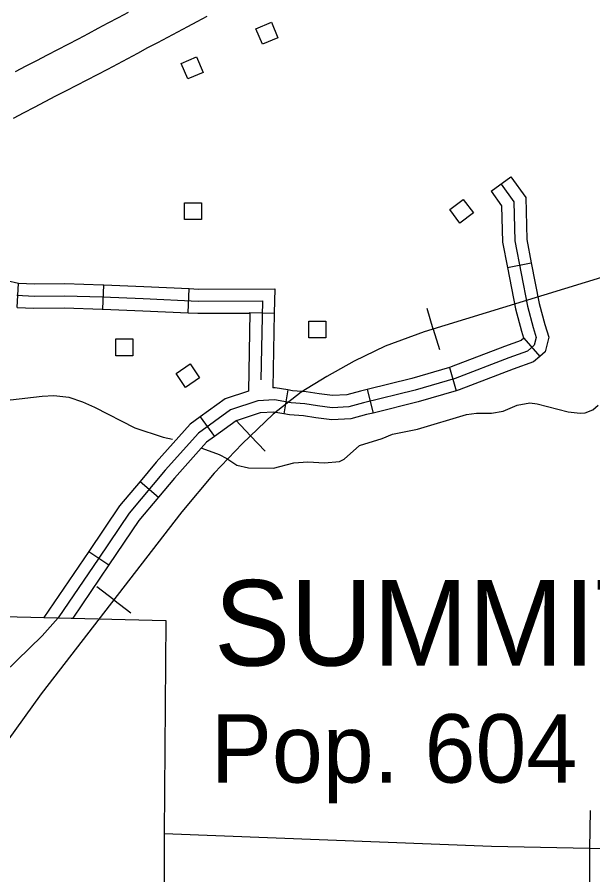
# Model space of a CAD drawing. Extents: x 1370130 to 1380143, y 377636 to 380256.
# Drawn here: x 1378630.1 to 1378779.4, y 378462.7 to 378685.1 of the extents above; entities that cross this region are included whole.
import ezdxf

# ---------------------------------------------------------------- set-up
doc = ezdxf.new("R2010")
doc.units = 0
for name, color, linetype in [('Level 10', 7, 'Continuous'), ('Level 32', 7, 'Continuous'), ('Level 34', 7, 'Continuous'), ('Level 35', 7, 'Continuous'), ('Level 40', 7, 'Continuous'), ('Level 5', 7, 'Continuous'), ('Level 56', 7, 'Continuous'), ('Level 6', 7, 'Continuous')]:
    doc.layers.add(name, color=color, linetype=linetype)

msp = doc.modelspace()

# ---------------------------------------------------------------- linework, layer by layer
at = {"layer": 'Level 10'}
for p, q in [((1378656.35, 378684.95), (1378658.96, 378686.34)), ((1378653.74, 378683.57), (1378656.35, 378684.95)), ((1378679.24, 378685.21), (1378676.72, 378683.89)), ((1378648.56, 378680.81), (1378651.14, 378682.18)), ((1378651.14, 378682.18), (1378653.74, 378683.57)), ((1378674.23, 378682.56), (1378671.69, 378681.2)), ((1378676.72, 378683.89), (1378674.23, 378682.56)), ((1378645.99, 378679.45), (1378648.56, 378680.81)), ((1378669.1, 378679.83), (1378666.49, 378678.45)), ((1378671.69, 378681.2), (1378669.1, 378679.83)), ((1378640.68, 378676.69), (1378643.36, 378678.08)), ((1378643.36, 378678.08), (1378645.99, 378679.45)), ((1378666.49, 378678.45), (1378663.89, 378677.07)), ((1378635.21, 378673.87), (1378637.97, 378675.29)), ((1378637.97, 378675.29), (1378640.68, 378676.69)), ((1378661.27, 378675.68), (1378658.67, 378674.3)), ((1378663.89, 378677.07), (1378661.27, 378675.68)), ((1378632.43, 378672.43), (1378635.21, 378673.87)), ((1378656.09, 378672.92), (1378653.49, 378671.53)), ((1378658.67, 378674.3), (1378656.09, 378672.92)), ((1378629.67, 378670.99), (1378632.43, 378672.43)), ((1378653.49, 378671.53), (1378650.86, 378670.14)), ((1378648.2, 378668.77), (1378645.52, 378667.37)), ((1378650.86, 378670.14), (1378648.2, 378668.77)), ((1378645.52, 378667.37), (1378642.78, 378665.95)), ((1378640.02, 378664.54), (1378637.28, 378663.12)), ((1378642.78, 378665.95), (1378640.02, 378664.54)), ((1378634.54, 378661.68), (1378631.81, 378660.25)), ((1378637.28, 378663.12), (1378634.54, 378661.68)), ((1378631.81, 378660.25), (1378629.07, 378658.82))]:
    msp.add_line(p, q, dxfattribs=at)
at = {"layer": 'Level 32'}
for p, q in [((1378752.99, 378639.94), (1378758.1, 378643.63)), ((1378757.22, 378620.19), (1378763.4, 378621.39)), ((1378630.1, 378609.83), (1378630.42, 378616.12)), ((1378652.29, 378609.39), (1378652.56, 378615.68)), ((1378674.43, 378608.4), (1378674.73, 378614.7)), ((1378690.46, 378608.48), (1378696.76, 378608.37)), ((1378761.48, 378601.87), (1378765.58, 378597.09)), ((1378742.16, 378594.24), (1378743.93, 378588.2)), ((1378700.29, 378588.42), (1378699.2, 378582.21)), ((1378720.87, 378588.56), (1378722.38, 378582.44)), ((1378677.56, 378581.45), (1378681.26, 378576.35)), ((1378661.96, 378564.72), (1378666.78, 378560.66)), ((1378648.68, 378546.57), (1378653.91, 378543.06))]:
    msp.add_line(p, q, dxfattribs=at)
for points in [[(1378755.55, 378641.79), (1378758.84, 378637.23), (1378759.09, 378627.1), (1378762.38, 378610.14), (1378763.9, 378604.57), (1378764.66, 378602.03), (1378764.15, 378600.01), (1378762.38, 378598.49), (1378757.57, 378596.72), (1378743.65, 378591.4), (1378733.28, 378588.36), (1378719.87, 378585.07), (1378716.07, 378584.06), (1378711.77, 378583.8), (1378707.97, 378584.31), (1378704.68, 378584.82), (1378701.14, 378585.07), (1378696.84, 378585.83), (1378692.54, 378585.58), (1378685.45, 378583.3), (1378677.1, 378577.22), (1378668.5, 378567.6), (1378659.13, 378556.46), (1378651.29, 378544.81), (1378640.77, 378529.36)], [(1378758.1, 378643.63), (1378761.96, 378638.28), (1378762.23, 378627.44), (1378763.4, 378621.39)], [(1378752.99, 378639.94), (1378755.71, 378636.18), (1378755.95, 378626.76), (1378757.22, 378620.19)], [(1378608.42, 378617.41), (1378609.35, 378619.85), (1378610.88, 378621.69), (1378612.97, 378622.64), (1378615.22, 378622.64), (1378616.61, 378622.09), (1378618.14, 378621.37), (1378621.24, 378619.38), (1378623.98, 378618.1), (1378627.42, 378616.76), (1378630.46, 378616.12), (1378630.42, 378616.12)], [(1378757.22, 378620.19), (1378759.31, 378609.42), (1378760.87, 378603.7), (1378761.39, 378601.96), (1378761.34, 378601.75), (1378761.48, 378601.87)], [(1378763.4, 378621.39), (1378765.45, 378610.85), (1378766.93, 378605.43), (1378767.92, 378602.11), (1378766.96, 378598.27), (1378765.58, 378597.09)], [(1378630.42, 378616.12), (1378634.56, 378615.92), (1378642.43, 378615.99), (1378652.34, 378615.69), (1378652.56, 378615.68)], [(1378652.56, 378615.68), (1378662.93, 378615.25), (1378674.73, 378614.7)], [(1378630.06, 378612.99), (1378634.49, 378612.77), (1378642.4, 378612.84), (1378652.22, 378612.54), (1378662.79, 378612.1), (1378677.05, 378611.44), (1378693.67, 378611.51), (1378693.3, 378591.03)], [(1378674.73, 378614.7), (1378677.11, 378614.59), (1378696.88, 378614.67), (1378696.76, 378608.37)], [(1378630.1, 378609.83), (1378634.43, 378609.62), (1378642.36, 378609.69), (1378652.11, 378609.4), (1378652.29, 378609.39)], [(1378652.29, 378609.39), (1378662.65, 378608.95), (1378674.43, 378608.4)], [(1378674.43, 378608.4), (1378676.98, 378608.29), (1378690.46, 378608.35), (1378690.46, 378608.48)], [(1378690.46, 378608.48), (1378690.1, 378588.1)], [(1378696.76, 378608.37), (1378696.41, 378588.96)], [(1378761.48, 378601.87), (1378760.76, 378601.25), (1378756.46, 378599.67), (1378742.65, 378594.39), (1378742.16, 378594.24)], [(1378765.58, 378597.09), (1378764, 378595.73), (1378758.68, 378593.77), (1378744.66, 378588.41), (1378743.93, 378588.2)], [(1378742.16, 378594.24), (1378732.46, 378591.4), (1378720.87, 378588.56)], [(1378700.29, 378588.42), (1378697.02, 378589), (1378696.41, 378588.96)], [(1378720.87, 378588.56), (1378719.09, 378588.12), (1378715.57, 378587.18), (1378711.89, 378586.97), (1378708.42, 378587.43), (1378705.04, 378587.95), (1378701.53, 378588.2), (1378700.29, 378588.42)], [(1378690.1, 378588.1), (1378684.01, 378586.14), (1378677.56, 378581.45)], [(1378743.93, 378588.2), (1378734.1, 378585.32), (1378722.38, 378582.44)], [(1378699.2, 378582.21), (1378696.66, 378582.66), (1378693.12, 378582.45), (1378686.9, 378580.45), (1378681.26, 378576.35)], [(1378722.38, 378582.44), (1378720.65, 378582.02), (1378716.57, 378580.93), (1378711.65, 378580.64), (1378707.53, 378581.19), (1378704.33, 378581.68), (1378700.75, 378581.94), (1378699.2, 378582.21)], [(1378677.56, 378581.45), (1378674.98, 378579.57), (1378666.12, 378569.66), (1378661.96, 378564.72)], [(1378681.26, 378576.35), (1378679.23, 378574.87), (1378670.88, 378565.54), (1378666.78, 378560.66)], [(1378661.96, 378564.72), (1378656.62, 378558.36), (1378648.68, 378546.57)], [(1378666.78, 378560.66), (1378661.65, 378554.56), (1378653.91, 378543.06)], [(1378648.68, 378546.57), (1378637.02, 378529.45), (1378644.52, 378529.27)], [(1378653.91, 378543.06), (1378653.9, 378543.05), (1378644.52, 378529.27)]]:
    msp.add_lwpolyline(points, dxfattribs=at)
at = {"layer": 'Level 34'}
msp.add_lwpolyline([(1378640.77, 378529.36), (1378636.57, 378524.7), (1378626.74, 378515.08)], dxfattribs=at)
at = {"layer": 'Level 35'}
for points in [[(1378620.81, 378587.18), (1378623.05, 378586.51), (1378628.36, 378585.86), (1378636.59, 378586.82), (1378639.6, 378586.97), (1378643.47, 378586.52), (1378647.04, 378585.35), (1378650.15, 378583.99), (1378660.61, 378578.56), (1378667.95, 378576.22), (1378670.39, 378575.64)], [(1378724.73, 378575.87), (1378727.39, 378576.95), (1378733.93, 378578.29), (1378746.63, 378582.03), (1378749.23, 378582.4), (1378753.1, 378582.39), (1378756.12, 378582.96), (1378759.74, 378584.49), (1378763.05, 378585.1), (1378764.96, 378584.8), (1378772.96, 378582.75), (1378776.03, 378582.41)], [(1378776.03, 378582.41), (1378777.34, 378582.46), (1378779.32, 378583.28), (1378780.75, 378584.47)], [(1378690.08, 378568.23), (1378696.59, 378568.16), (1378701.83, 378569.57), (1378705.43, 378569.8), (1378709.77, 378569.57), (1378713.68, 378569.91), (1378714.92, 378570.48), (1378718.88, 378574.04), (1378724.73, 378575.87)], [(1378677.99, 378573.34), (1378682.45, 378571.69), (1378684.5, 378570.67), (1378687.04, 378568.91), (1378690.08, 378568.23)]]:
    msp.add_lwpolyline(points, dxfattribs=at)
at = {"layer": 'Level 40'}
for p, q in [((1378737.99, 378604.22), (1378736.37, 378609.52)), ((1378737.99, 378604.22), (1378739.61, 378598.92)), ((1378690.6, 378576.55), (1378686.78, 378580.56)), ((1378690.6, 378576.55), (1378694.43, 378572.54)), ((1378655.15, 378534), (1378650.77, 378537.39)), ((1378655.15, 378534), (1378659.54, 378530.61))]:
    msp.add_line(p, q, dxfattribs=at)
msp.add_lwpolyline([(1379037.67, 378728.08), (1379011.37, 378711.43), (1378979.03, 378691.2), (1378955.14, 378676.03), (1378944.66, 378670.61), (1378929.78, 378663.71), (1378913.88, 378657.74), (1378900.65, 378653.42), (1378885.95, 378648.73), (1378808.4, 378625.74), (1378735.63, 378603.5), (1378725.52, 378599.73), (1378717.44, 378595.87), (1378710.36, 378591.91), (1378703.75, 378587.87), (1378696.49, 378582.17), (1378688.4, 378574.44), (1378681.14, 378566.81), (1378672.78, 378556.79), (1378636.31, 378509.63), (1378616.64, 378482.33), (1378598.45, 378460.26)], dxfattribs=at)
msp.add_lwpolyline([(1379037.67, 378728.08), (1379011.37, 378711.43), (1378979.03, 378691.2), (1378955.14, 378676.03), (1378944.66, 378670.61), (1378929.78, 378663.71), (1378913.88, 378657.74), (1378900.65, 378653.42), (1378885.95, 378648.73), (1378808.4, 378625.74), (1378735.63, 378603.5), (1378725.52, 378599.73), (1378717.44, 378595.87), (1378710.36, 378591.91), (1378703.75, 378587.87), (1378696.49, 378582.17), (1378688.4, 378574.44), (1378681.14, 378566.81), (1378672.78, 378556.79), (1378636.31, 378509.63), (1378616.64, 378482.33), (1378598.45, 378460.26)], dxfattribs=at)
at = {"layer": 'Level 5'}
for points in [[(1378778.64, 378479.41), (1378778.51, 378469.55)], [(1378778.51, 378469.55), (1378753.11, 378470.11), (1378668.24, 378473.37)], [(1378778.51, 378469.55), (1378778.23, 378387.25)], [(1378891.42, 378467.73), (1378834.76, 378468.48), (1378778.51, 378469.55)]]:
    msp.add_lwpolyline(points, dxfattribs=at)
at = {"layer": 'Level 56'}
for points in [[(1378693.67, 378678.03), (1378691.98, 378682.06), (1378696.03, 378683.75), (1378697.72, 378679.72)], [(1378672.6, 378673.09), (1378676.62, 378674.79), (1378678.34, 378670.76), (1378674.31, 378669.05)], [(1378745.75, 378637.83), (1378748.37, 378634.33), (1378744.86, 378631.7), (1378742.24, 378635.2)], [(1378673.47, 378632.57), (1378673.47, 378636.94), (1378677.86, 378636.94), (1378677.86, 378632.57)], [(1378705.72, 378601.89), (1378705.72, 378606.26), (1378710.1, 378606.26), (1378710.1, 378601.89)], [(1378655.68, 378597.3), (1378655.68, 378601.67), (1378660.07, 378601.67), (1378660.07, 378597.3)], [(1378674.95, 378595.15), (1378677.41, 378591.54), (1378673.78, 378589.07), (1378671.32, 378592.69)]]:
    msp.add_lwpolyline(points, close=True, dxfattribs=at)
at = {"layer": 'Level 6'}
msp.add_lwpolyline([(1378577.46, 378530.92), (1378668.67, 378528.67), (1378668.24, 378473.37), (1378668.14, 378390.77), (1378778.23, 378387.25), (1378778.14, 378362.19)], dxfattribs=at)

# ---------------------------------------------------------------- texts
for s, height, p in [('SUMMIT', 22.176, (1378681.14, 378516.96)), ('Pop. 604', 17.741, (1378680.33, 378486.63))]:
    msp.add_text(s, height=height, dxfattribs=at).set_placement(p)

doc.saveas('drawing.dxf')
